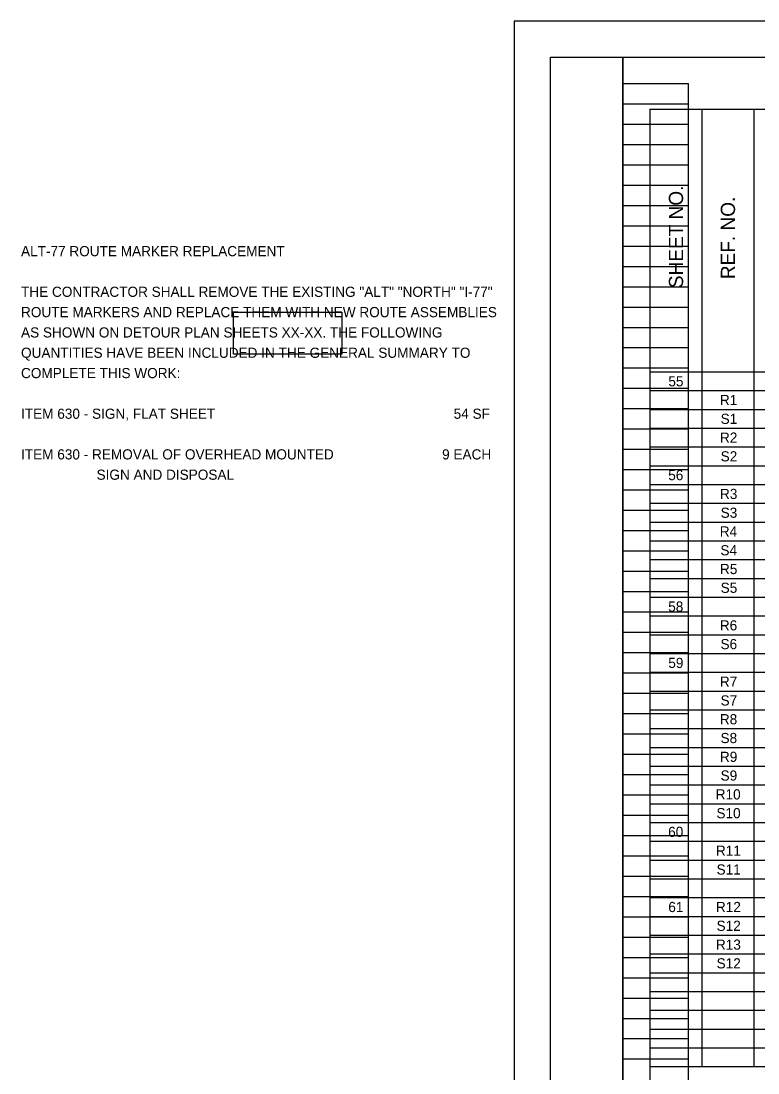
# Model space of a CAD drawing. Extents: x -6.8 to 34, y 0 to 22.
# Drawn here: x -6.79 to 3.36, y 7.51 to 22 of the extents above; entities that cross this region are included whole.
import ezdxf

# ---------------------------------------------------------------- set-up
doc = ezdxf.new("R2010")
doc.units = 0
for name, color, linetype in [('SC_Scratch1', 7, 'Continuous'), ('SH_Border', 7, 'Continuous'), ('SH_Cut_Line', 7, 'Continuous'), ('SH_Data', 7, 'Continuous'), ('SH_Text', 7, 'Continuous')]:
    doc.layers.add(name, color=color, linetype=linetype)

msp = doc.modelspace()

# ---------------------------------------------------------------- linework, layer by layer
at = {"layer": 'SC_Scratch1'}
msp.add_lwpolyline([(-3.863, 17.988), (-2.372, 17.988), (-2.372, 17.412), (-3.863, 17.412)], close=True, dxfattribs=at)
at = {"layer": 'SH_Border'}
for points in [[(0.5, 21.5), (1.5, 21.5), (1.5, 0.5), (0.5, 0.5)], [(1.5, 21.5), (33.5, 21.5), (33.5, 0.5), (1.5, 0.5)]]:
    msp.add_lwpolyline(points, close=True, dxfattribs=at)
at = {"layer": 'SH_Cut_Line'}
msp.add_lwpolyline([(0, 0), (34, 0), (34, 22), (0, 22)], close=True, dxfattribs=at)
at = {"layer": 'SH_Data'}
for p, q in [((1.5, 0.98), (1.5, 21.14)), ((1.5, 21.14), (2.4, 21.14)), ((2.4, 0.98), (2.4, 21.14)), ((1.5, 20.86), (2.4, 20.86)), ((1.5, 20.58), (2.4, 20.58)), ((1.5, 20.3), (2.4, 20.3)), ((1.5, 20.02), (2.4, 20.02)), ((1.5, 19.74), (2.4, 19.74)), ((1.5, 19.46), (2.4, 19.46)), ((1.5, 19.18), (2.4, 19.18)), ((1.5, 18.9), (2.4, 18.9)), ((1.5, 18.62), (2.4, 18.62)), ((1.5, 18.34), (2.4, 18.34)), ((1.5, 18.06), (2.4, 18.06)), ((1.5, 17.78), (2.4, 17.78)), ((1.5, 17.5), (2.4, 17.5)), ((1.5, 17.22), (2.4, 17.22)), ((1.5, 16.94), (2.4, 16.94)), ((1.5, 16.66), (2.4, 16.66)), ((1.5, 16.38), (2.4, 16.38)), ((1.5, 16.1), (2.4, 16.1)), ((1.5, 15.82), (2.4, 15.82)), ((1.5, 15.54), (2.4, 15.54)), ((1.5, 15.26), (2.4, 15.26)), ((1.5, 14.98), (2.4, 14.98)), ((1.5, 14.7), (2.4, 14.7)), ((1.5, 14.42), (2.4, 14.42)), ((1.5, 14.14), (2.4, 14.14)), ((1.5, 13.86), (2.4, 13.86)), ((1.5, 13.58), (2.4, 13.58)), ((1.5, 13.3), (2.4, 13.3)), ((1.5, 13.02), (2.4, 13.02)), ((1.5, 12.74), (2.4, 12.74)), ((1.5, 12.46), (2.4, 12.46)), ((1.5, 12.18), (2.4, 12.18)), ((1.5, 11.9), (2.4, 11.9)), ((1.5, 11.62), (2.4, 11.62)), ((1.5, 11.34), (2.4, 11.34)), ((1.5, 11.06), (2.4, 11.06)), ((1.5, 10.78), (2.4, 10.78)), ((1.5, 10.5), (2.4, 10.5)), ((1.5, 10.22), (2.4, 10.22)), ((1.5, 9.94), (2.4, 9.94)), ((1.5, 9.66), (2.4, 9.66)), ((1.5, 9.38), (2.4, 9.38)), ((1.5, 9.1), (2.4, 9.1)), ((1.5, 8.82), (2.4, 8.82)), ((1.5, 8.54), (2.4, 8.54)), ((1.5, 8.26), (2.4, 8.26)), ((1.5, 7.98), (2.4, 7.98)), ((1.5, 7.7), (2.4, 7.7))]:
    msp.add_line(p, q, dxfattribs=at)
at = {"layer": 'SH_Text'}
for p, q in [((1.872, 20.788), (16.435, 20.788)), ((1.872, 20.788), (1.872, 7.078)), ((2.588, 20.788), (2.588, 7.595)), ((3.303, 20.788), (3.303, 7.595)), ((1.872, 17.167), (16.435, 17.167)), ((1.872, 16.908), (16.435, 16.908)), ((1.872, 16.649), (16.435, 16.649)), ((1.872, 16.391), (16.435, 16.391)), ((1.872, 16.132), (16.435, 16.132)), ((1.872, 15.873), (16.435, 15.873)), ((1.872, 15.615), (16.435, 15.615)), ((1.872, 15.356), (16.435, 15.356)), ((1.872, 15.097), (16.435, 15.097)), ((1.872, 14.838), (16.435, 14.838)), ((1.872, 14.58), (16.435, 14.58)), ((1.872, 14.321), (16.435, 14.321)), ((1.872, 14.062), (16.435, 14.062)), ((1.872, 13.804), (16.435, 13.804)), ((1.872, 13.545), (16.435, 13.545)), ((1.872, 13.286), (16.435, 13.286)), ((1.872, 13.028), (16.435, 13.028)), ((1.872, 12.769), (16.435, 12.769)), ((1.872, 12.51), (16.435, 12.51)), ((1.872, 12.251), (16.435, 12.251)), ((1.872, 11.993), (16.435, 11.993)), ((1.872, 11.734), (16.435, 11.734)), ((1.872, 11.475), (16.435, 11.475)), ((1.872, 11.217), (16.435, 11.217)), ((1.872, 10.958), (16.435, 10.958)), ((1.872, 10.699), (16.435, 10.699)), ((1.872, 10.441), (16.435, 10.441)), ((1.872, 10.182), (16.435, 10.182)), ((1.872, 9.923), (16.435, 9.923)), ((1.872, 9.665), (16.435, 9.665)), ((1.872, 9.406), (16.435, 9.406)), ((1.872, 9.147), (16.435, 9.147)), ((1.872, 8.888), (16.435, 8.888)), ((1.872, 8.63), (16.435, 8.63)), ((1.872, 8.371), (16.435, 8.371)), ((1.872, 8.112), (16.435, 8.112)), ((1.872, 7.854), (16.435, 7.854)), ((1.872, 7.595), (9.192, 7.595))]:
    msp.add_line(p, q, dxfattribs=at)

# ---------------------------------------------------------------- texts
for s, p in [('SHEET NO.', (2.328, 18.32)), ('REF. NO.', (3.043, 18.444))]:
    msp.add_text(s, height=0.196, rotation=90, dxfattribs=at).set_placement(p)
for s, p in [('ALT-77 ROUTE MARKER REPLACEMENT', (-6.79, 18.76)), ('THE CONTRACTOR SHALL REMOVE THE EXISTING "ALT" "NORTH" "I-77" ', (-6.79, 18.2)), ('ROUTE MARKERS AND REPLACE THEM WITH NEW ROUTE ASSEMBLIES ', (-6.79, 17.92)), ('AS SHOWN ON DETOUR PLAN SHEETS XX-XX. THE FOLLOWING ', (-6.79, 17.64)), ('QUANTITIES HAVE BEEN INCLUDED IN THE GENERAL SUMMARY TO ', (-6.79, 17.36)), ('COMPLETE THIS WORK:', (-6.79, 17.08)), ('55', (2.125, 16.967)), ('R1', (2.835, 16.709)), ('ITEM 630 - SIGN, FLAT SHEET', (-6.79, 16.52)), ('54 SF', (-0.832, 16.52)), ('S1', (2.845, 16.45)), ('R2', (2.836, 16.191)), ('ITEM 630 - REMOVAL OF OVERHEAD MOUNTED', (-6.79, 15.96)), ('9 EACH', (-0.991, 15.96)), ('S2', (2.845, 15.933)), ('                    SIGN AND DISPOSAL', (-6.79, 15.68)), ('56', (2.123, 15.674)), ('R3', (2.836, 15.415)), ('S3', (2.845, 15.156)), ('R4', (2.833, 14.898)), ('S4', (2.842, 14.639)), ('R5', (2.836, 14.38)), ('S5', (2.845, 14.122)), ('58', (2.123, 13.863)), ('R6', (2.834, 13.604)), ('S6', (2.843, 13.346)), ('59', (2.124, 13.087)), ('R7', (2.835, 12.828)), ('S7', (2.844, 12.57)), ('R8', (2.834, 12.311)), ('S8', (2.843, 12.052)), ('R9', (2.835, 11.793)), ('S9', (2.844, 11.535)), ('R10', (2.777, 11.276)), ('S10', (2.787, 11.017)), ('60', (2.122, 10.759)), ('R11', (2.78, 10.5)), ('S11', (2.789, 10.241)), ('61', (2.124, 9.724)), ('R12', (2.78, 9.724)), ('S12', (2.789, 9.465)), ('R13', (2.78, 9.206)), ('S12', (2.789, 8.948))]:
    msp.add_text(s, height=0.14, dxfattribs=at).set_placement(p)

doc.saveas('drawing.dxf')
